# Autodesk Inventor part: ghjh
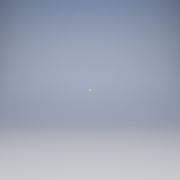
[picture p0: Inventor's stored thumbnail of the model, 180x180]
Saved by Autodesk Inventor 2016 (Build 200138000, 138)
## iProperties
Created: 2016-06
Part Number: ghjh
Material: Genérico
Document SubType Name: Modeling
Designer: adm
Density: 1 g/cm^3
Appearance: Valor por defecto
Author: adm
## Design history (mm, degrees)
sketch "Boceto1"
  geometry: 1 further point
  constraints: 1 other
